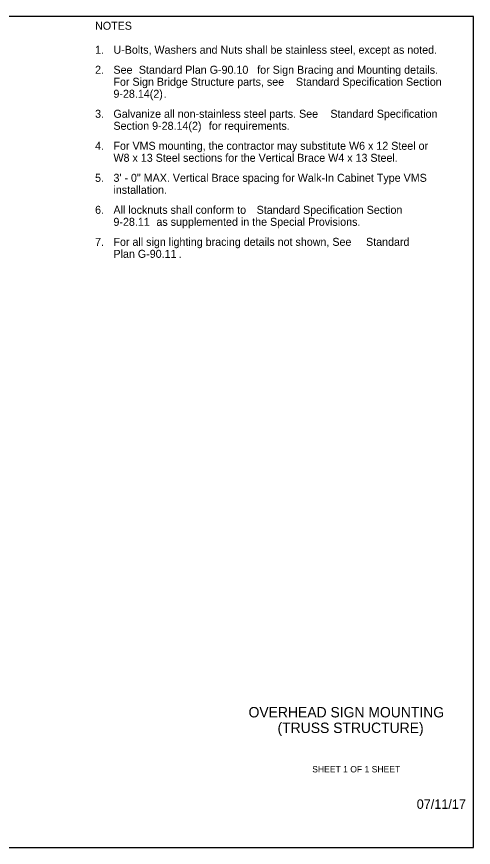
# Model space of a CAD drawing. Extents: x 99862 to 103151, y 100000 to 102076.
# Drawn here: x 102009 to 103151, y 100000 to 102076 of the extents above; entities that cross this region are included whole.
import ezdxf

# ---------------------------------------------------------------- set-up
doc = ezdxf.new("R2010")
doc.units = 0
for name, color, linetype in [('Level 1', 7, 'Continuous'), ('Level 15', 7, 'Continuous'), ('Level 20', 7, 'Continuous'), ('Level 60', 7, 'Continuous'), ('Level 62', 7, 'Continuous')]:
    doc.layers.add(name, color=color, linetype=linetype)

msp = doc.modelspace()

# ---------------------------------------------------------------- linework, layer by layer
at = {"layer": 'Level 1'}
msp.add_lwpolyline([(99862, 99999.5), (103151, 99999.5), (103151, 102075.5), (99862, 102075.5)], close=True, dxfattribs=at)
at = {"layer": 'Level 60'}
msp.add_line((103151, 102075.5), (103151, 102075.5), dxfattribs=at)

# ---------------------------------------------------------------- texts
at = {"layer": 'Level 1'}
for s, p in [('U-Bolts, Washers and Nuts shall be stainless steel, except as noted.', (102251.5, 101982.7)), ('See ', (102251.5, 101932.7)), ('Standard Plan G-90.10', (102315, 101932.7)), (' for Sign Bracing and Mounting details.', (102603.3, 101932.7)), ('For Sign Bridge Structure parts, see ', (102251.5, 101902.7)), ('Standard Specification Section', (102707.5, 101902.7)), ('9-28.14(2)', (102251.5, 101872.7)), ('.', (102376.9, 101872.7)), ('Galvanize all non-stainless steel parts. See ', (102251.5, 101822.7)), ('Standard Specification', (102793.6, 101822.7)), ('Section 9-28.14(2)', (102251.5, 101792.7)), (' for requirements.', (102482.5, 101792.7)), ('For VMS mounting, the contractor may substitute W6 x 12 Steel or', (102251.5, 101742.7)), ('W8 x 13 Steel sections for the Vertical Brace W4 x 13 Steel.', (102251.5, 101712.7)), ('3\' - 0" MAX. Vertical Brace spacing for Walk-In Cabinet Type VMS', (102251.5, 101662.7)), ('installation.', (102251.5, 101632.7)), ('All locknuts shall conform to ', (102251.5, 101582.7)), ('Standard Specification Section', (102609.3, 101582.7)), ('9-28.11 ', (102251.5, 101552.7)), ('as supplemented in the Special Provisions.', (102358.8, 101552.7)), ('For all sign lighting bracing details not shown, See ', (102251.5, 101502.7)), ('Standard', (102882.7, 101502.7)), ('Plan G-90.11', (102251.5, 101472.7)), ('.', (102414.6, 101472.7))]:
    msp.add_text(s, height=20, dxfattribs=at).set_placement(p)
at = {"layer": 'Level 15'}
msp.add_text('07/11/17', height=23.62, dxfattribs=at).set_placement((103009.4, 100095.8))
at = {"layer": 'Level 20'}
for s, p in [('NOTES', (102205.6, 102042.7)), ('1.', (102205.6, 101982.7)), ('2.', (102205.6, 101932.7)), ('3.', (102205.6, 101822.7)), ('4.', (102205.6, 101742.7)), ('5.', (102205.6, 101662.7)), ('6.', (102205.6, 101582.7)), ('7.', (102205.6, 101502.7))]:
    msp.add_text(s, height=20, dxfattribs=at).set_placement(p)
at = {"layer": 'Level 62'}
for s, height, p in [('OVERHEAD SIGN MOUNTING', 26, (102589.1, 100324.3)), ('(TRUSS STRUCTURE)', 26, (102661.6, 100285.3)), ('SHEET 1 OF 1 SHEET', 16, (102748.2, 100186.8))]:
    msp.add_text(s, height=height, dxfattribs=at).set_placement(p)

doc.saveas('drawing.dxf')
